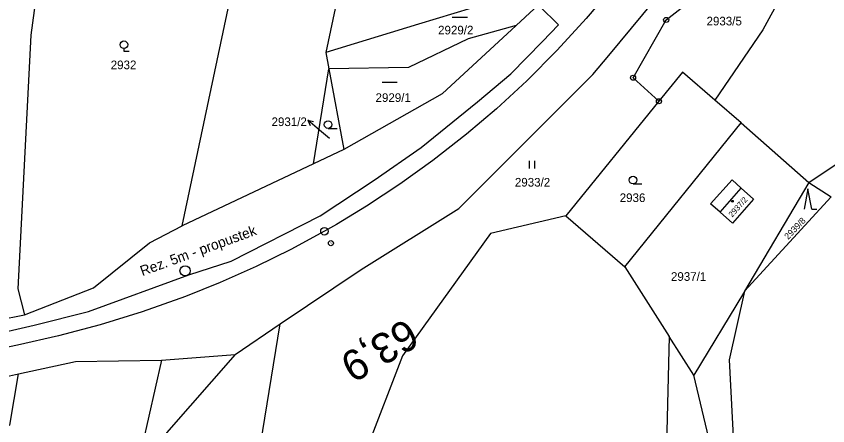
# Model space of a CAD drawing. Extents: x -620552 to -620056, y -1123312 to -1122890.
# Drawn here: x -620295.9 to -620136.2, y -1123118.1 to -1123037.5 of the extents above; entities that cross this region are included whole.
import ezdxf

# ---------------------------------------------------------------- set-up
doc = ezdxf.new("R2010")
doc.units = 0
for name, color, linetype in [('HranDP', 7, 'Continuous'), ('Hranice parcel', 7, 'Continuous'), ('Parcelní čísla', 7, 'Continuous'), ('Pop  PČ popisy', 7, 'Continuous'), ('Vnitřní kresba', 7, 'Continuous'), ('Vrstva 1', 7, 'Continuous'), ('Vrstva 13', 7, 'Continuous'), ('Vrstva 3', 7, 'Continuous'), ('Vrstva 7', 7, 'Continuous'), ('Značky bodu BP', 7, 'Continuous'), ('Značky budov', 7, 'Continuous'), ('Značky kultur', 7, 'Continuous')]:
    doc.layers.add(name, color=color, linetype=linetype)

msp = doc.modelspace()

# ---------------------------------------------------------------- linework, layer by layer
at = {"layer": 'HranDP'}
for p, q in [((-620192.2, -1123034.39), (-620197.49, -1123039.27)), ((-620231.41, -1123063.68), (-620237.39, -1123066.51)), ((-620237.39, -1123066.51), (-620263.28, -1123078.74)), ((-620306.69, -1123098.69), (-620294.3, -1123096.22)), ((-620252.85, -1123104.02), (-620243.96, -1123098.03)), ((-620267.31, -1123105.13), (-620252.85, -1123104.02)), ((-620301.93, -1123109.26), (-620295.45, -1123107.86))]:
    msp.add_line(p, q, dxfattribs=at)
for points in [[(-620243.96, -1123098.03), (-620228.02, -1123087.3), (-620208.81, -1123075.27), (-620182.41, -1123048.95), (-620179.31, -1123045.19), (-620168.12, -1123031.65)], [(-620197.49, -1123039.27), (-620212.08, -1123052.71), (-620231.41, -1123063.68)], [(-620294.3, -1123096.22), (-620280.71, -1123090.89), (-620269.72, -1123082.03), (-620263.28, -1123078.74)], [(-620295.45, -1123107.86), (-620284.26, -1123105.43), (-620267.31, -1123105.13)]]:
    msp.add_lwpolyline(points, dxfattribs=at)
at = {"layer": 'Hranice parcel'}
for p, q in [((-620218.17, -1122964.05), (-620234.98, -1123044.6)), ((-620263.28, -1123078.74), (-620242.46, -1122980.18)), ((-620136.85, -1123017.81), (-620148.96, -1123040.16)), ((-620192.2, -1123034.39), (-620197.49, -1123039.27)), ((-620148.96, -1123040.16), (-620158.39, -1123054.01)), ((-620234.98, -1123044.6), (-620234.38, -1123047.81)), ((-620237.39, -1123066.51), (-620234.38, -1123047.81)), ((-620234.38, -1123047.81), (-620231.41, -1123063.68)), ((-620169.42, -1123054.19), (-620187.77, -1123076.72)), ((-620153.24, -1123058.46), (-620158.39, -1123054.01)), ((-620176.15, -1123086.79), (-620153.24, -1123058.46)), ((-620153.24, -1123058.46), (-620139.89, -1123070.16)), ((-620231.41, -1123063.68), (-620237.39, -1123066.51)), ((-620237.39, -1123066.51), (-620263.28, -1123078.74)), ((-620139.89, -1123070.16), (-620152.59, -1123091.6)), ((-620187.77, -1123076.72), (-620176.15, -1123086.79)), ((-620176.15, -1123086.79), (-620167.39, -1123100.52)), ((-620152.59, -1123091.6), (-620152.8, -1123091.95)), ((-620152.8, -1123091.95), (-620162.55, -1123108.1)), ((-620306.69, -1123098.69), (-620294.3, -1123096.22)), ((-620258.49, -1123186.41), (-620243.96, -1123098.03)), ((-620252.85, -1123104.02), (-620243.96, -1123098.03)), ((-620167.39, -1123100.52), (-620169.58, -1123182.3)), ((-620162.55, -1123108.1), (-620167.39, -1123100.52)), ((-620267.31, -1123105.13), (-620252.85, -1123104.02)), ((-620301.93, -1123109.26), (-620295.45, -1123107.86))]:
    msp.add_line(p, q, dxfattribs=at)
for points in [[(-620289.02, -1123011.5), (-620293.05, -1123041.17), (-620295.61, -1123091.1), (-620294.3, -1123096.22)], [(-620169.42, -1123054.19), (-620174.5, -1123049.57), (-620168, -1123038.2), (-620152.59, -1123026.13)], [(-620243.96, -1123098.03), (-620228.02, -1123087.3), (-620208.81, -1123075.27), (-620182.41, -1123048.95), (-620179.31, -1123045.19), (-620168.12, -1123031.65)], [(-620194.62, -1123031.45), (-620202.81, -1123034.81), (-620216.72, -1123039.04), (-620234.98, -1123044.6)], [(-620197.49, -1123039.27), (-620207, -1123041.9), (-620218.72, -1123047.54), (-620234.38, -1123047.81)], [(-620197.49, -1123039.27), (-620212.08, -1123052.71), (-620231.41, -1123063.68)], [(-620139.89, -1123070.16), (-620126.22, -1123060.97), (-620107.28, -1123049.5), (-620100.81, -1123045.29)], [(-620158.39, -1123054.01), (-620164.78, -1123048.5), (-620169.42, -1123054.19)], [(-620159.28, -1123074.39), (-620154.99, -1123069.68), (-620153.24, -1123071.27), (-620150.78, -1123073.44), (-620154.95, -1123078.2), (-620157.37, -1123076.03), (-620159.28, -1123074.39)], [(-620139.89, -1123070.16), (-620135.5, -1123072.99), (-620152.59, -1123091.6)], [(-620187.77, -1123076.72), (-620202.59, -1123080.2), (-620219.89, -1123104.3), (-620226.94, -1123122.55), (-620232.45, -1123152.64), (-620233.85, -1123191.46)], [(-620294.3, -1123096.22), (-620280.71, -1123090.89), (-620269.72, -1123082.03), (-620263.28, -1123078.74)], [(-620152.59, -1123091.6), (-620155.57, -1123105.08), (-620154.07, -1123134.06), (-620143.02, -1123154.56), (-620138.08, -1123176.89), (-620193.14, -1123193.74), (-620221.59, -1123191.7), (-620233.71, -1123192.88), (-620259.81, -1123191.23)], [(-620252.85, -1123104.02), (-620266.37, -1123119.45), (-620267.54, -1123124.06), (-620286.24, -1123150.98), (-620288.99, -1123164.76), (-620262.29, -1123185.63)], [(-620267.31, -1123105.13), (-620271.09, -1123121.69), (-620283, -1123136.04), (-620303.5, -1123155.32)], [(-620295.45, -1123107.86), (-620284.26, -1123105.43), (-620267.31, -1123105.13)], [(-620298.49, -1123117.9), (-620297.19, -1123117.91), (-620295.45, -1123107.86)], [(-620169.58, -1123182.3), (-620139.22, -1123177.02), (-620156.05, -1123135.37), (-620162.55, -1123108.1)]]:
    msp.add_lwpolyline(points, dxfattribs=at)
at = {"layer": 'Pop  PČ popisy'}
for p, q in [((-620236.21, -1123059.88), (-620238.51, -1123057.95)), ((-620238.51, -1123057.95), (-620237.42, -1123058.21)), ((-620238.51, -1123057.95), (-620238.06, -1123058.98)), ((-620234.25, -1123061.52), (-620236.21, -1123059.88))]:
    msp.add_line(p, q, dxfattribs=at)
at = {"layer": 'Vnitřní kresba'}
msp.add_line((-620157.37, -1123076.03), (-620153.24, -1123071.27), dxfattribs=at)
at = {"layer": 'Vrstva 1'}
for points in [[(-620302.99, -1123100.7), (-620292.4, -1123098.24), (-620281.7, -1123095.56), (-620261.93, -1123088.35), (-620253.64, -1123085.66), (-620236.13, -1123076.73), (-620225.47, -1123069.74), (-620216.19, -1123063.28), (-620205.15, -1123054.34), (-620198.59, -1123048.78), (-620192.32, -1123042.45), (-620189.21, -1123039.13), (-620192.93, -1123035.47), (-620189.24, -1123032.05), (-620184.32, -1123027.49), (-620172.92, -1123014.85), (-620170.12, -1123011.86), (-620165.72, -1123007.16), (-620158.18, -1122991.64), (-620154.53, -1122984.74), (-620154, -1122982.93), (-620152.3, -1122977.09), (-620150.63, -1122971.37)], [(-620178.73, -1123032.03), (-620183.71, -1123037.93), (-620189.42, -1123044.16), (-620195.41, -1123050.18), (-620201.42, -1123055.71), (-620207.3, -1123060.67), (-620213.93, -1123065.85), (-620220.45, -1123070.54), (-620226.96, -1123074.82), (-620232.91, -1123078.44), (-620235.25, -1123079.78), (-620241.89, -1123083.37), (-620248.71, -1123086.73), (-620255.76, -1123089.87), (-620262.62, -1123092.63), (-620271.12, -1123095.65), (-620279.4, -1123098.2), (-620287.58, -1123100.35), (-620295.67, -1123102.19), (-620303.02, -1123103.7)]]:
    msp.add_lwpolyline(points, dxfattribs=at)
at = {"layer": 'Vrstva 13'}
msp.add_circle((-620262.69, -1123087.56), 1, dxfattribs=at)
at = {"layer": 'Vrstva 7'}
msp.add_line((-620233.94, -1123082.09), (-620234.03, -1123082.14), dxfattribs=at)
for centre, radius in [((-620235.25, -1123079.78), 0.75), ((-620233.98, -1123082.12), 0.5)]:
    msp.add_circle(centre, radius, dxfattribs=at)
at = {"layer": 'Značky bodu BP'}
for centre, radius in [((-620168, -1123038.2), 0.5), ((-620168, -1123038.2), 0.0303), ((-620174.5, -1123049.57), 0.5), ((-620174.5, -1123049.57), 0.0303), ((-620169.42, -1123054.19), 0.5), ((-620169.42, -1123054.19), 0.0303)]:
    msp.add_circle(centre, radius, dxfattribs=at)
at = {"layer": 'Značky budov'}
msp.add_circle((-620154.96, -1123073.88), 0.175, dxfattribs=at)
at = {"layer": 'Značky kultur'}
for p, q in [((-620210.09, -1123037.67), (-620207.09, -1123037.67)), ((-620274.72, -1123043.82), (-620274.72, -1123044.32)), ((-620274.72, -1123044.32), (-620273.72, -1123044.32)), ((-620223.92, -1123050.46), (-620220.92, -1123050.46)), ((-620234.53, -1123059.54), (-620232.78, -1123059.54)), ((-620194.87, -1123067.42), (-620194.87, -1123065.92)), ((-620193.87, -1123067.42), (-620193.87, -1123065.92)), ((-620174.52, -1123070.46), (-620172.77, -1123070.46)), ((-620140.1, -1123071.45), (-620140.85, -1123075.45)), ((-620139.35, -1123075.45), (-620140.1, -1123071.45)), ((-620139.35, -1123075.45), (-620138.35, -1123075.45))]:
    msp.add_line(p, q, dxfattribs=at)
for centre in [(-620274.72, -1123043.07), (-620234.53, -1123058.79), (-620174.52, -1123069.71)]:
    msp.add_circle(centre, 0.75, dxfattribs=at)

# ---------------------------------------------------------------- texts
at = {"layer": 'Parcelní čísla'}
for s, p in [('2933/5', (-620160.05, -1123039.27)), ('2929/2', (-620212.89, -1123041.04)), ('2932', (-620277.33, -1123047.89)), ('2929/1', (-620225.2, -1123054.33)), ('2931/2', (-620245.67, -1123059.08)), ('2933/2', (-620197.77, -1123070.99)), ('2936', (-620177.14, -1123074.03)), ('2937/1', (-620167.05, -1123089.54))]:
    msp.add_text(s, height=1.7, dxfattribs=at).set_placement(p)
for s, height, rotation, p in [('2937/2', 1.139, 48, (-620155, -1123077.11)), ('2939/8', 1.254, 46, (-620143.98, -1123081.5))]:
    msp.add_text(s, height=height, rotation=rotation, dxfattribs=at).set_placement(p)
at = {"layer": 'Vrstva 3'}
msp.add_text('Rez. 5m - propustek', height=2, rotation=19.9058, dxfattribs=at).set_placement((-620271.1, -1123088.62))
at = {"layer": 'Vrstva 7'}
msp.add_text('63,9', height=6, rotation=209.9159, dxfattribs=at).set_placement((-620219.08, -1123096.76))

doc.saveas('drawing.dxf')
